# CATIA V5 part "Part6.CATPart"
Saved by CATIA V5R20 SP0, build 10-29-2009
Part number: 9FP1808M6
Revision: ANY
Definition: UNKNOWN
Nomenclature: 9FP1808M6
Source: Unknown
Bounding box of the stored display mesh (mm): x -8.9 to 8.9, y 0 to 8, z -8.9 to 8.9
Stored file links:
  C:\Users\Utente\Desktop\IO LAVORO\3D X SITO CF\CUMSA\3D files PW\pw101630\pw101630_injection\Part6.CATPart
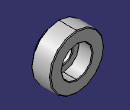
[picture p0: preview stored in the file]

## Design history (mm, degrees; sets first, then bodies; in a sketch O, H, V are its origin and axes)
Body1 "Chaflán1" (main body)
  Solid1: solid without history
